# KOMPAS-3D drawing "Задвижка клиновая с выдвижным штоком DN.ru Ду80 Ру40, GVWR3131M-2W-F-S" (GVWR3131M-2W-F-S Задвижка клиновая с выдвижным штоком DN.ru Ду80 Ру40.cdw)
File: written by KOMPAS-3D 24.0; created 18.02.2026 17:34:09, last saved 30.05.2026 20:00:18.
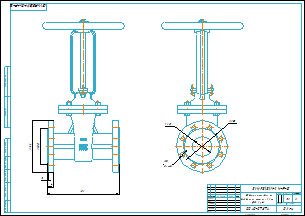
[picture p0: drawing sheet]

Document properties: art: D040-08596; Автор: R2D2; Форматы листов документа: A2; Полное имя файла: GVWR3131M-2W-F-S Задвижка клиновая с выдвижным штоком DN.ru Ду80 Ру40.m3d; Масса: 31; Наименование: Задвижка клиновая с выдвижным штоком DN.ru Ду80 Ру40; Количество листов документа: 1; Примечание: D040-07874

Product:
- Part/product: Задвижка клиновая с выдвижным штоком DN.ru Ду80 Ру40  | designation GVWR3131M-2W-F-S
    Масса: 31
    Раздел спецификации: Прочие изделия
    Примечание: D040-07874

Views: Вид 1, Справа
Referenced files in E:\Работа\Зайцев\GVWR3131M-2W-F-S Задвижка клиновая с выдвижным штоком DN.ru Ду50-200 Ру63\DN80\: GVWR3131M-2W-F-S Задвижка клиновая с выдвижным штоком DN.ru Ду80 Ру63.m3d
Referenced files in E:\Работа\Зайцев\GVWR3131M-2W-F-S Задвижка клиновая с выдвижным штоком DN.ru Ду50-100 Ру40\исходные материалы\DN80\DN80\: GVWR3131M-2W-F-S Задвижка клиновая с выдвижным штоком DN.ru Ду80 Ру40.m3d
Referenced files in E:\Работа\Зайцев\Для компаса\: чертеж DN.ru А3.cdt
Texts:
  GVWR3131M-2W-F-S
  чертеж DN.ru А3.cdt
  Задвижка клиновая с
  выдвижным штоком DN.ru
  Ду80 Ру40
  Задвижка клиновая с выдвижным штоком DN.ru Ду80 Ру40
  GVWR3131M-2W-F-S Задвижка клиновая с выдвижным штоком DN.ru Ду80 Ру40
Dimensions and other numbers on the sheet: 0; 3; 2; 4; 280; 24; 200; 138; 1:2; 1; 31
